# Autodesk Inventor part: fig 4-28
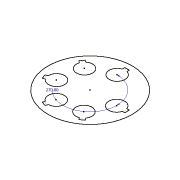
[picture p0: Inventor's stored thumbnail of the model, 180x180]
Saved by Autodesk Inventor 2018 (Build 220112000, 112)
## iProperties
Created: 2004-05
Part Number: fig 4-28
Document SubType Name: Modeling
Designer: CADCIM Technologies
Manufacturer: Standard
Standards Organization: Custom
Density: 1 g/cm^3
Material: Generic
Appearance: Default
Author: CADCIM Technologies
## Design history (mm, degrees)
sketch "Sketch2"
  geometry: L1 (0.73, 11.049)-(0.73, 11.828); L2 (0.73, 11.828)-(-0.73, 11.828); L3 (-0.73, 11.828)-(-0.73, 11.006); L4 (-0.152, 11.061)-(0.73, 11.828); L5 (0.152, 11.061)-(-0.73, 11.828); L6 (-8.51, 7.085)-(-9.14, 7.543); L7 (-9.14, 7.543)-(-9.998, 6.362); L8 (-9.998, 6.362)-(-9.333, 5.879); L9 (-9.038, 6.378)-(-9.14, 7.543); L10 (-8.859, 6.625)-(-9.998, 6.362); L11 (-10.734, -2.72)-(-11.474, -2.961); L12 (-11.474, -2.961)-(-11.023, -4.349); L13 (-11.023, -4.349)-(-10.242, -4.095); L14 (-10.472, -3.563)-(-11.474, -2.961); L15 (-10.566, -3.273)-(-11.023, -4.349); L16 (-4.108, -10.283)-(-4.349, -11.023); L17 (-4.349, -11.023)-(-2.961, -11.474); L18 (-2.961, -11.474)-(-2.707, -10.693); L19 (-3.273, -10.566)-(-4.349, -11.023); L20 (-3.563, -10.472)-(-2.961, -11.474); L21 (5.904, -9.368)-(6.362, -9.998); L22 (6.362, -9.998)-(7.543, -9.14); L23 (7.543, -9.14)-(7.06, -8.475); L24 (6.625, -8.859)-(6.362, -9.998); L25 (6.378, -9.038)-(7.543, -9.14); L26 (11.049, -0.73)-(11.828, -0.73); L27 (11.828, -0.73)-(11.828, 0.73); L28 (11.828, 0.73)-(11.006, 0.73); L29 (11.061, 0.152)-(11.828, -0.73); L30 (11.061, -0.152)-(11.828, 0.73); C1 r 13.473 at (0, 0); A1 r 2.558 centre (0.072, 8.577) between (-0.73, 11.006) and (0.73, 11.049); A2 r 2.558 centre (-6.897, 5.1) between (-9.333, 5.879) and (-8.51, 7.085); A3 r 2.558 centre (-8.18, -2.582) between (-10.242, -4.095) and (-10.734, -2.72); A4 r 2.558 centre (-2.719, -8.135) between (-2.707, -10.693) and (-4.108, -10.283); A5 r 2.558 centre (4.983, -6.981) between (7.06, -8.475) and (5.904, -9.368); A6 r 2.558 centre (8.577, -0.072) between (11.006, 0.73) and (11.049, -0.73); 6 further points
  constraints: 60 end point, 12 point on circle, 7 centre point, 2 coincident, 1 parallel, 70 other
  dimensions: "d6" = 270 deg dimension on point (0, 0) A1.centre A6.centre
